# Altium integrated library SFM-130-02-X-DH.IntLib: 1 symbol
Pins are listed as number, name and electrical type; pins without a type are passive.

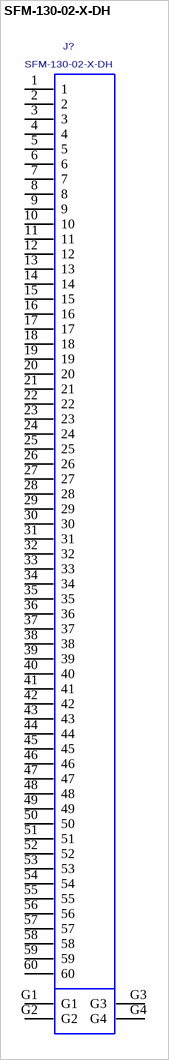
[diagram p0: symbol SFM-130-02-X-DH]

## SFM-130-02-X-DH
designator J?
.050" (1,27mm) Tiger Eye Contact, Molded-to-Position Socket Strip, Double Horizontal.; MANUFACTURER: SAMTEC
footprint SFM-130-02-X-DH (Footprint not found)
pins: 1, 2, 3, 4, 5, 6, 7, 8, 9, 10, 11, 12, 13, 14, 15, 16, 17, 18, 19, 20, 21, 22, 23, 24, 25, 26, 27, 28, 29, 30, 31, 32, 33, 34, 35, 36, 37, 38, 39, 40, 41, 42, 43, 44, 45, 46, 47, 48, 49, 50, 51, 52, 53, 54, 55, 56, 57, 58, 59, 60, G1, G2, G3, G4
